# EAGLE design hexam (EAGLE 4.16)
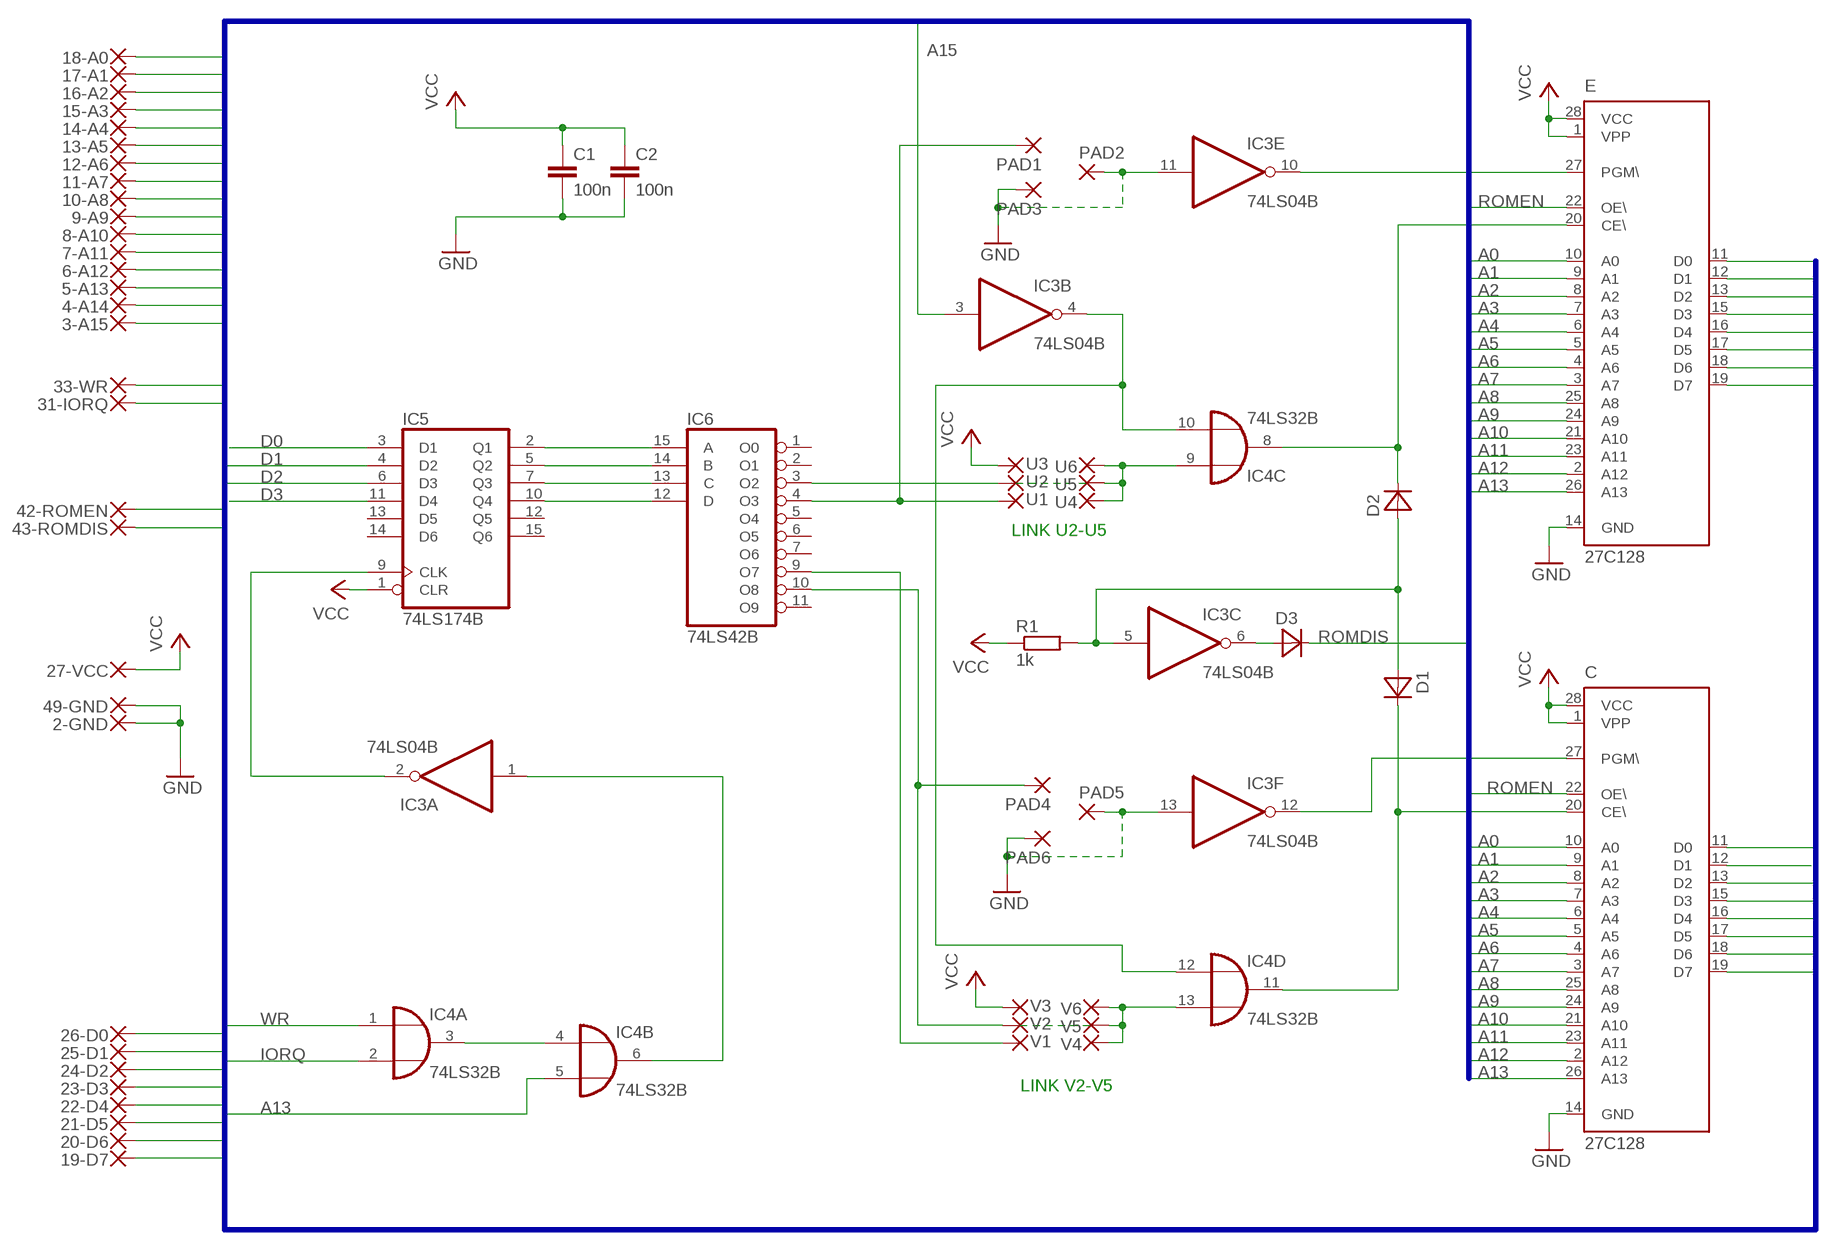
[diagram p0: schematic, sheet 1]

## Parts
2-GND  1,27-REDONDO0.8  [1,27/0,8-REDONDO]
3-A15  1,27-REDONDO0.8  [1,27/0,8-REDONDO]
4-A14  1,27-REDONDO0.8  [1,27/0,8-REDONDO]
5-A13  1,27-REDONDO0.8  [1,27/0,8-REDONDO]
6-A12  1,27-REDONDO0.8  [1,27/0,8-REDONDO]
7-A11  1,27-REDONDO0.8  [1,27/0,8-REDONDO]
8-A10  1,27-REDONDO0.8  [1,27/0,8-REDONDO]
9-A9  1,27-REDONDO0.8  [1,27/0,8-REDONDO]
10-A8  1,27-REDONDO0.8  [1,27/0,8-REDONDO]
11-A7  1,27-REDONDO0.8  [1,27/0,8-REDONDO]
12-A6  1,27-REDONDO0.8  [1,27/0,8-REDONDO]
13-A5  1,27-REDONDO0.8  [1,27/0,8-REDONDO]
14-A4  1,27-REDONDO0.8  [1,27/0,8-REDONDO]
15-A3  1,27-REDONDO0.8  [1,27/0,8-REDONDO]
16-A2  1,27-REDONDO0.8  [1,27/0,8-REDONDO]
17-A1  1,27-REDONDO0.8  [1,27/0,8-REDONDO]
18-A0  1,27-REDONDO0.8  [1,27/0,8-REDONDO]
19-D7  1,27-REDONDO0.8  [1,27/0,8-REDONDO]
20-D6  1,27-REDONDO0.8  [1,27/0,8-REDONDO]
21-D5  1,27-REDONDO0.8  [1,27/0,8-REDONDO]
22-D4  1,27-REDONDO0.8  [1,27/0,8-REDONDO]
23-D3  1,27-REDONDO0.8  [1,27/0,8-REDONDO]
24-D2  1,27-REDONDO0.8  [1,27/0,8-REDONDO]
25-D1  1,27-REDONDO0.8  [1,27/0,8-REDONDO]
26-D0  1,27-REDONDO0.8  [1,27/0,8-REDONDO]
27-VCC  1,27-REDONDO0.8  [1,27/0,8-REDONDO]
31-IORQ  1,27-REDONDO0.8  [1,27/0,8-REDONDO]
33-WR  1,27-REDONDO0.8  [1,27/0,8-REDONDO]
42-ROMEN  1,27-REDONDO0.8  [1,27/0,8-REDONDO]
43-ROMDIS  1,27-REDONDO0.8  [1,27/0,8-REDONDO]
49-GND  1,27-REDONDO0.8  [1,27/0,8-REDONDO]
C  27C128  27128B  [DIL28-6B]
C1  100n  C-EU050-025X075  [C050-025X075]
C2  100n  C-EU050-025X075  [C050-025X075]
D1  DIODE-7,5  [D-7,5]
D2  DIODE-7,5  [D-7,5]
D3  DIODE-7,5  [D-7,5]
E  27C128  27128B  [DIL28-6B]
IC3  74LS04B  [DIL14-B]
IC4  74LS32B  [DIL14-B]
IC5  74LS174B  [DIL16-B]
IC6  74LS42B  [DIL16-B]
PAD1  SMD2  [SMD1,27-2,54]
PAD2  SMD2  [SMD1,27-2,54]
PAD3  SMD2  [SMD1,27-2,54]
PAD4  SMD2  [SMD1,27-2,54]
PAD5  SMD2  [SMD1,27-2,54]
PAD6  SMD2  [SMD1,27-2,54]
R1  1k  R-EU_0207/7  [0207/7]
U1  1,27-REDONDO0.8  [1,27/0,8-REDONDO]
U2  1,27-REDONDO0.8  [1,27/0,8-REDONDO]
U3  1,27-REDONDO0.8  [1,27/0,8-REDONDO]
U4  1,27-REDONDO0.8  [1,27/0,8-REDONDO]
U5  1,27-REDONDO0.8  [1,27/0,8-REDONDO]
U6  1,27-REDONDO0.8  [1,27/0,8-REDONDO]
V1  1,27-REDONDO0.8  [1,27/0,8-REDONDO]
V2  1,27-REDONDO0.8  [1,27/0,8-REDONDO]
V3  1,27-REDONDO0.8  [1,27/0,8-REDONDO]
V4  1,27-REDONDO0.8  [1,27/0,8-REDONDO]
V5  1,27-REDONDO0.8  [1,27/0,8-REDONDO]
V6  1,27-REDONDO0.8  [1,27/0,8-REDONDO]

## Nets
A0: 18-A0.1(P) C.10(A0) E.10(A0)
A1: 17-A1.1(P) C.9(A1) E.9(A1)
A2: 16-A2.1(P) C.8(A2) E.8(A2)
A3: 15-A3.1(P) C.7(A3) E.7(A3)
A4: 14-A4.1(P) C.6(A4) E.6(A4)
A5: 13-A5.1(P) C.5(A5) E.5(A5)
A6: 12-A6.1(P) C.4(A6) E.4(A6)
A7: 11-A7.1(P) C.3(A7) E.3(A7)
A8: 10-A8.1(P) C.25(A8) E.25(A8)
A9: 9-A9.1(P) C.24(A9) E.24(A9)
A10: 8-A10.1(P) C.21(A10) E.21(A10)
A11: 7-A11.1(P) C.23(A11) E.23(A11)
A12: 6-A12.1(P) C.2(A12) E.2(A12)
A13: 5-A13.1(P) C.26(A13) E.26(A13) IC4.5(B:I1)
A14: 4-A14.1(P)
A15: 3-A15.1(P) IC3.3(B:I)
D0: 26-D0.1(P) C.11(D0) E.11(D0) IC5.3(D1)
D1: 25-D1.1(P) C.12(D1) E.12(D1) IC5.4(D2)
D2: 24-D2.1(P) C.13(D2) E.13(D2) IC5.6(D3)
D3: 23-D3.1(P) C.15(D3) E.15(D3) IC5.11(D4)
D4: 22-D4.1(P) C.16(D4) E.16(D4)
D5: 21-D5.1(P) C.17(D5) E.17(D5)
D6: 20-D6.1(P) C.18(D6) E.18(D6)
D7: 19-D7.1(P) C.19(D7) E.19(D7)
GND: 2-GND.1(P) 49-GND.1(P) C1.2 C2.2 C.14(GND) E.14(GND) IC3.11(E:I) IC3.13(F:I) PAD2.1(P) PAD3.1(P) PAD5.1(P) PAD6.1(P)
IORQ: 31-IORQ.1(P) IC4.2(A:I1)
N$5: D1.1(A) D2.1(A) IC3.5(C:I) R1.2
N$12: D3.1(A) IC3.6(C:O)
N$24: C.27(PGM\) IC3.12(F:O)
N$25: D2.2(K) E.20(CE\) IC4.8(C:O)
N$26: E.27(PGM\) IC3.10(E:O)
N$27: IC6.10(O8) PAD4.1(P) V2.1(P)
N$28: IC6.9(O7) V1.1(P)
N$30: IC5.2(Q1) IC6.15(A)
N$31: IC5.5(Q2) IC6.14(B)
N$32: IC5.7(Q3) IC6.13(C)
N$33: IC3.2(A:O) IC5.9(CLK)
N$34: IC6.4(O3) PAD1.1(P) U1.1(P)
N$35: IC6.3(O2) U2.1(P)
N$36: IC4.9(C:I0) U4.1(P) U5.1(P) U6.1(P)
N$37: IC3.1(A:I) IC4.6(B:O)
N$38: IC3.4(B:O) IC4.10(C:I1) IC4.12(D:I0)
N$39: IC4.3(A:O) IC4.4(B:I0)
N$40: IC4.13(D:I1) V4.1(P) V5.1(P) V6.1(P)
N$41: C.20(CE\) D1.2(K) IC4.11(D:O)
N$43: IC5.10(Q4) IC6.12(D)
ROMDIS: 43-ROMDIS.1(P) D3.2(K)
ROMEN: 42-ROMEN.1(P) C.22(OE\) E.22(OE\)
VCC: 27-VCC.1(P) C1.1 C2.1 C.1(VPP) C.28(VCC) E.1(VPP) E.28(VCC) IC5.1(CLR) R1.1 U3.1(P) V3.1(P)
WR: 33-WR.1(P) IC4.1(A:I0)
Unconnected: IC3.8(D:O) IC3.9(D:I) IC5.12(Q5) IC5.13(D5) IC5.14(D6) IC5.15(Q6) IC6.1(O0) IC6.2(O1) IC6.5(O4) IC6.6(O5) IC6.7(O6) IC6.11(O9)

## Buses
A[0..15],WR,IORQ,D[0..7],ROMEN,ROMDIS

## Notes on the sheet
- LINK U2-U5
- LINK V2-V5

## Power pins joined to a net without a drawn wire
GND: IC3.7(P:GND) IC4.7(P:GND) IC5.8(GND) IC6.8(GND)
VCC: IC3.14(P:VCC) IC4.14(P:VCC) IC5.16(VCC) IC6.16(VCC)

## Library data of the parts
2-GND 3-A15 4-A14 5-A13 6-A12 7-A11 8-A10 9-A9 10-A8 11-A7 12-A6 13-A5 14-A4 15-A3 16-A2 17-A1 18-A0 19-D7 20-D6 21-D5 22-D4 23-D3 24-D2 25-D1 26-D0 27-VCC 31-IORQ 33-WR 42-ROMEN 43-ROMDIS 49-GND U1-U6 V1-V6 = wirepad2:1,27-REDONDO
C E = microchip:27*128: CMOS EPROM 128 K (16 K x 8)
C1 C2 = rcl:C-EU: CAPACITOR, European symbol
D1-D3 = discrete2:DIODE-7,5
IC3 = 74xx-eu2:74*04: Hex INVERTER
IC4 = 74xx-eu2:74*32: Quad 2-input OR gate
IC5 = 74xx-eu2:74*174: Hex D type FLIP FLOP, clear
IC6 = 74xx-eu2:74*42: 4-line to 10-line DECODER (1-of-10)
PAD1-PAD6 = wirepad:SMD2: SMD PAD
R1 = rcl:R-EU_: RESISTOR, European symbol

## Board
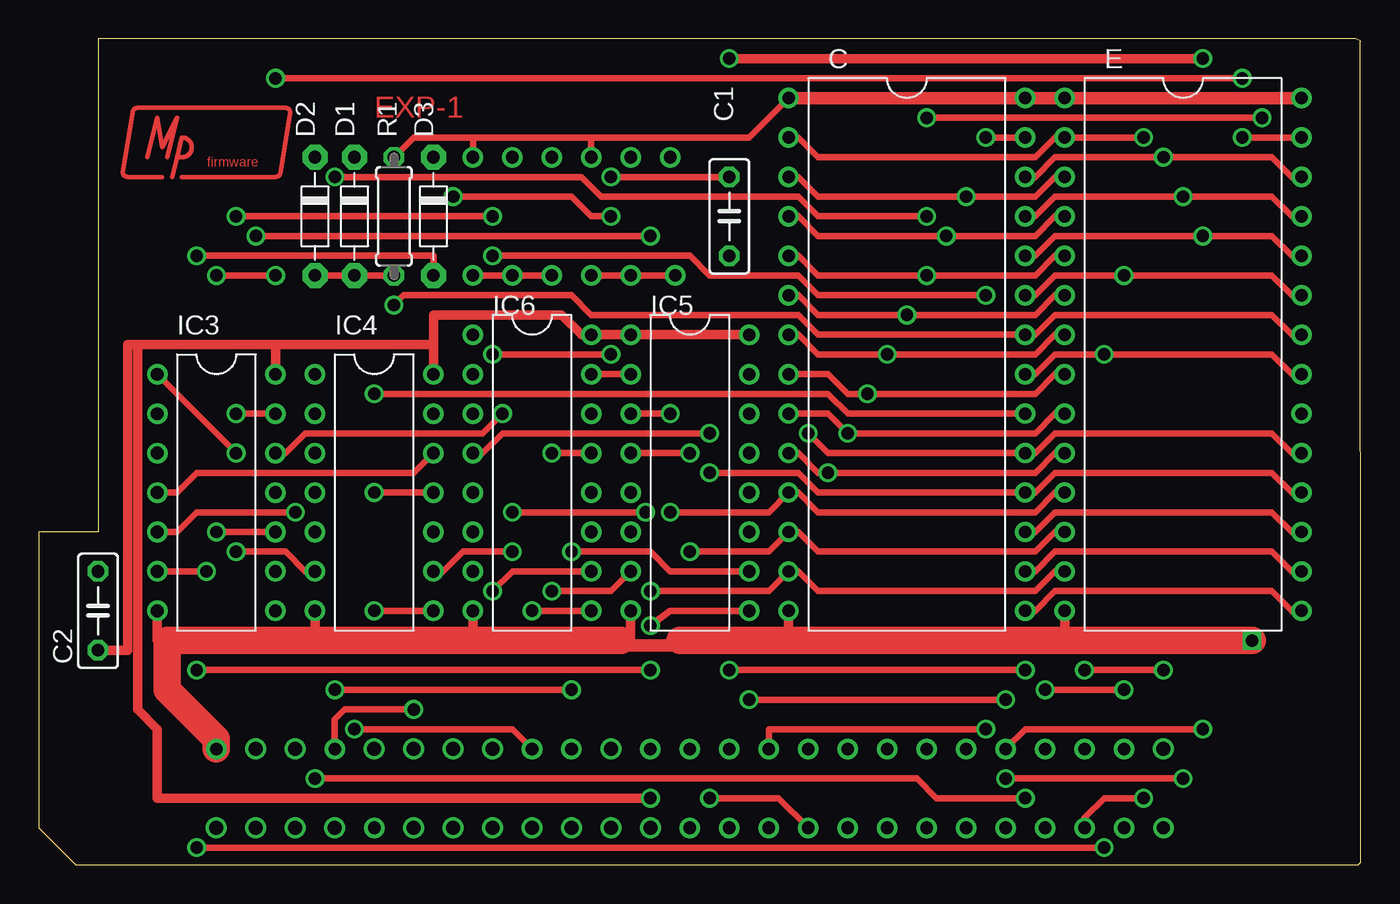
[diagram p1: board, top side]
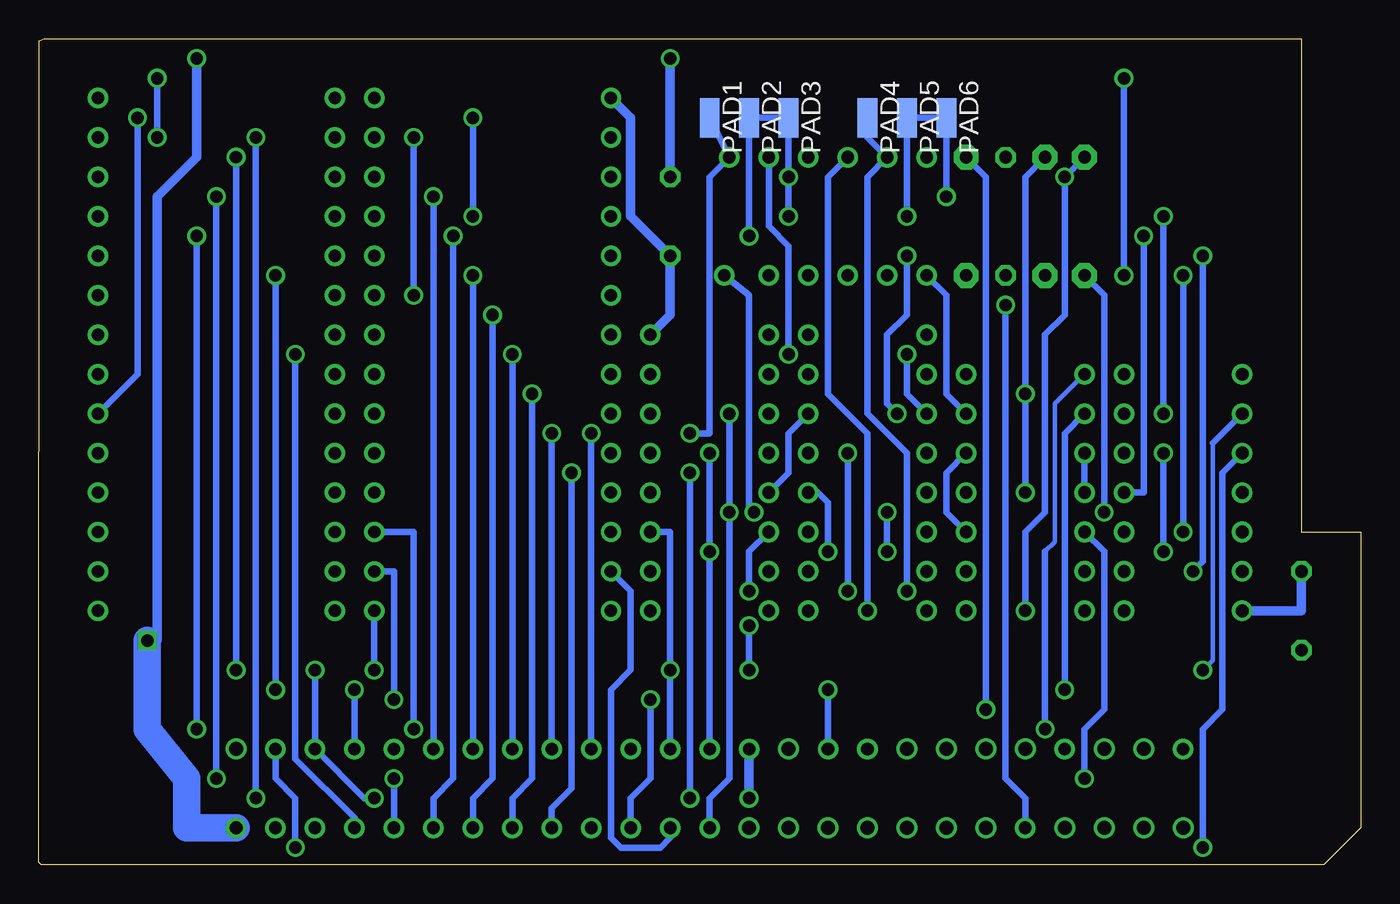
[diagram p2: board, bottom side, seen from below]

Size 85.09 x 53.18 mm. Coordinates in mm from the lower left corner, seen from the top.
Outline: 84.94,0 85.09,0.15 85.08,53.01 85.09,53.01 84.77,53.18 3.81,53.18 3.81,21.43 0,21.43 0,2.38 2.38,0 84.94,0
Copper layers (1*16): Top 0.035mm / dielectric 1.5mm / Bottom 0.035mm
Design rules "default": minimum track width 10mil, minimum drill 24mil, track to track 8mil, track to pad 8mil, pad to pad 8mil, via to via 8mil, smd to smd 8mil, copper to edge 40mil, drill to drill 8mil, minimum pad ring 10mil, minimum via ring 8mil, stop-mask expansion 4mil, vias tented up to drill 0mil, thermal gap 10mil

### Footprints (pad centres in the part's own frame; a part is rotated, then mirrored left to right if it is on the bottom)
1,27/0,8-REDONDO = drill 0.813 pad 1.27 round: 1 0,0
DIL28-6B = drill 0.8 round: 1 -16.51,-7.62; 2 -13.97,-7.62; 3 -11.43,-7.62; 4 -8.89,-7.62; 5 -6.35,-7.62; 6 -3.81,-7.62; 7 -1.27,-7.62; 8 1.27,-7.62; 9 3.81,-7.62; 10 6.35,-7.62; 11 8.89,-7.62; 12 11.43,-7.62; 13 13.97,-7.62; 14 16.51,-7.62; 15 16.51,7.62; 16 13.97,7.62; 17 11.43,7.62; 18 8.89,7.62; 19 6.35,7.62; 20 3.81,7.62; 21 1.27,7.62; 22 -1.27,7.62; 23 -3.81,7.62; 24 -6.35,7.62; 25 -8.89,7.62; 26 -11.43,7.62; 27 -13.97,7.62; 28 -16.51,7.62
C050-025X075 = drill 0.813 octagon: 1 -2.54,0; 2 2.54,0
D-7,5 = drill 0.813 pad 1.6 octagon: 1 -3.81,0; 2 3.81,0
DIL14-B = drill 0.813 round: 1 -7.62,-3.81; 2 -5.08,-3.81; 3 -2.54,-3.81; 4 0,-3.81; 5 2.54,-3.81; 6 5.08,-3.81; 7 7.62,-3.81; 8 7.62,3.81; 9 5.08,3.81; 10 2.54,3.81; 11 0,3.81; 12 -2.54,3.81; 13 -5.08,3.81; 14 -7.62,3.81
DIL16-B = drill 0.813 round: 1 -8.89,-3.81; 2 -6.35,-3.81; 3 -3.81,-3.81; 4 -1.27,-3.81; 5 1.27,-3.81; 6 3.81,-3.81; 7 6.35,-3.81; 8 8.89,-3.81; 9 8.89,3.81; 10 6.35,3.81; 11 3.81,3.81; 12 1.27,3.81; 13 -1.27,3.81; 14 -3.81,3.81; 15 -6.35,3.81; 16 -8.89,3.81
SMD1,27-2,54 = smd 1.27 x 2.54: 1 0,0
0207/7 = drill 0.813 octagon: 1 -3.81,0; 2 3.81,0

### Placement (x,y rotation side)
2-GND  72.39,2.38 180 top
3-A15  69.85,7.46 0 top
4-A14  69.85,2.38 180 top
5-A13  67.31,7.46 0 top
6-A12  67.31,2.38 180 top
7-A11  64.77,7.46 0 top
8-A10  64.77,2.38 180 top
9-A9  62.23,7.46 0 top
10-A8  62.23,2.38 180 top
11-A7  59.69,7.46 0 top
12-A6  59.69,2.38 180 top
13-A5  57.15,7.46 0 top
14-A4  57.15,2.38 180 top
15-A3  54.61,7.46 0 top
16-A2  54.61,2.38 180 top
17-A1  52.07,7.46 0 top
18-A0  52.07,2.38 180 top
19-D7  49.53,7.46 0 top
20-D6  49.53,2.38 180 top
21-D5  46.99,7.46 0 top
22-D4  46.99,2.38 180 top
23-D3  44.45,7.46 0 top
24-D2  44.45,2.38 180 top
25-D1  41.91,7.46 0 top
26-D0  41.91,2.38 180 top
27-VCC  39.37,7.46 0 top
31-IORQ  34.29,7.46 0 top
33-WR  31.75,7.46 0 top
42-ROMEN  21.59,2.38 180 top
43-ROMDIS  19.05,7.46 0 top
49-GND  11.43,7.46 0 top
C  55.88,32.86 270 top
C1  44.45,41.74 90 top
C2  3.81,16.35 90 top
D1  20.32,41.74 90 top
D2  17.78,41.74 90 top
D3  25.4,41.74 90 top
E  73.66,32.86 270 top
IC3  11.43,23.96 270 top
IC4  21.59,23.96 270 top
IC5  41.91,25.23 270 top
IC6  31.75,25.23 270 top
PAD1  41.91,48.09 180 bottom
PAD2  39.37,48.09 180 bottom
PAD3  36.83,48.09 180 bottom
PAD4  31.75,48.09 180 bottom
PAD5  29.21,48.09 180 bottom
PAD6  26.67,48.09 180 bottom
R1  22.86,41.74 270 top
U1  40.64,45.55 0 top
U2  38.1,45.55 0 top
U3  35.56,45.55 0 top
U4  40.96,37.94 0 top
U5  38.1,37.94 0 top
U6  35.56,37.94 0 top
V1  33.02,45.55 0 top
V2  30.48,45.55 0 top
V3  27.94,45.55 0 top
V4  27.94,37.94 0 top
V5  30.48,37.94 0 top
V6  33.02,37.94 0 top

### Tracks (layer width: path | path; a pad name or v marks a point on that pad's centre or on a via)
A0  (via drill 0.8)
  Top 0.406: E.10 65.41,26.51 64.14,25.23 v50.8,25.23 50.16,25.23 48.9,26.51 C.10
  Bottom 0.406: 18-A0.1 52.07,3.65 50.8,4.92 v50.8,25.23
A1  (via drill 0.8)
  Top 0.406: E.9 65.41,29.05 64.14,27.78 v52.07,27.78 50.8,29.05 C.9
  Bottom 0.406: 17-A1.1 v52.07,27.78
A2  (via drill 0.8)
  Top 0.406: E.8 65.41,31.59 64.14,30.32 v53.34,30.32 52.07,30.32 50.8,31.59 C.8
  Bottom 0.406: 16-A2.1 54.61,4.28 53.34,5.55 v53.34,30.32
A3  (via drill 0.8)
  Top 0.406: E.7 65.41,34.12 64.14,32.86 v54.61,32.86 50.16,32.86 48.9,34.12 C.7
  Bottom 0.406: 15-A3.1 v54.61,32.86
A4  (via drill 0.8)
  Top 0.406: E.6 65.41,36.66 64.14,35.4 v55.88,35.4 50.16,35.4 48.9,36.66 C.6
  Bottom 0.406: 14-A4.1 57.15,4.28 55.88,5.55 v55.88,35.4
A5  (via drill 0.8)
  Top 0.406: E.5 65.41,39.2 64.14,37.94 v57.15,37.94 50.16,37.94 48.9,39.2 C.5
  Bottom 0.406: 13-A5.1 v57.15,37.94
A6  (via drill 0.8)
  Top 0.406: E.4 65.41,41.74 64.14,40.48 v58.42,40.48 50.16,40.48 48.9,41.74 C.4
  Bottom 0.406: 12-A6.1 59.69,4.28 58.42,5.55 v58.42,40.48
A7  (via drill 0.8)
  Top 0.406: C.3 48.9,44.29 50.16,43.02 v59.69,43.02 64.14,43.02 65.41,44.29 E.3
  Bottom 0.406: 11-A7.1 v59.69,43.02
A8  (via drill 0.8)
  Top 0.406: E.25 80.64,41.74 79.38,43.02 v73.66,43.02 65.41,43.02 64.14,41.74 C.25 | v62.23,5.55 v73.66,5.55
  Bottom 0.406: v73.66,5.55 v73.66,43.02 | 10-A8.1 v62.23,5.55
A9  (via drill 0.8)
  Top 0.406: E.24 80.64,39.2 79.38,40.48 v74.93,40.48 65.41,40.48 64.14,39.2 C.24 | 9-A9.1 63.5,8.73 v74.93,8.73
  Bottom 0.406: v74.93,8.73 v74.93,40.48
A10  (via drill 0.8)
  Top 0.406: C.21 64.14,31.59 65.41,32.86 v68.58,32.86 79.38,32.86 80.64,31.59 E.21
  Bottom 0.406: 8-A10.1 64.77,3.01 68.58,6.82 v68.58,32.86
A11  (via drill 0.8)
  Top 0.406: E.23 80.64,36.66 79.38,37.94 v69.85,37.94 65.41,37.94 64.14,36.66 C.23 | v64.77,11.27 v69.85,11.27
  Bottom 0.406: 7-A11.1 v64.77,11.27 | v69.85,11.27 v69.85,37.94
A12  (via drill 0.8)
  Top 0.406: C.2 48.9,46.83 50.16,45.55 64.14,45.55 65.41,46.83 E.2 v71.12,46.83 | 6-A12.1 67.31,3.01 68.58,4.28 v71.12,4.28
  Bottom 0.406: v71.12,4.28 v71.12,46.83
A13  (via drill 0.8)
  Top 0.406: E.26 80.64,44.29 79.38,45.55 v72.39,45.55 65.41,45.55 64.14,44.29 C.26 | v67.31,12.54 v72.39,12.54 | v17.78,5.55 56.52,5.55 57.78,4.28 v63.5,4.28
  Bottom 0.406: v67.31,12.54 5-A13.1 64.14,4.28 v63.5,4.28 | v72.39,12.54 v72.39,45.55 | IC4.5 16.51,20.16 16.51,10 17.78,8.73 v17.78,5.55
A15  (via drill 0.8)
  Top 0.406: v10.16,1.1 v68.58,1.1
  Bottom 0.406: IC3.3 8.89,25.23 8.89,10 10.16,8.73 v10.16,1.1 | v68.58,1.1 68.58,4.28 69.85,5.55 3-A15.1
D0  (via drill 0.8)
  Top 0.406: E.11 65.41,23.96 64.14,22.7 50.16,22.7 48.9,23.96 C.11 46.99,22.7 v40.64,22.7 | v40.64,29.05 IC5.3
  Bottom 0.406: 26-D0.1 41.91,4.28 40.64,5.55 v40.64,22.7 v40.64,29.05
D1  (via drill 0.8)
  Top 0.406: E.12 65.41,21.43 64.14,20.16 50.16,20.16 48.9,21.43 C.12 46.99,20.16 v41.91,20.16 | v41.91,26.51 IC5.4
  Bottom 0.406: 25-D1.1 41.91,14.44 v41.91,20.16 v41.91,26.51
D2  (via drill 0.8)
  Top 0.406: E.13 65.41,18.89 64.14,17.62 50.16,17.62 48.9,18.89 C.13 46.99,17.62 v39.37,17.62
  Bottom 0.406: C.13 46.99,17.62 46.99,12.54 48.26,11.27 48.26,1.74 47.62,1.1 45.09,1.1 44.45,1.74 24-D2.1 | IC5.6 39.37,20.16 v39.37,17.62
D3  (via drill 0.8)
  Top 0.406: C.15 64.14,16.35 65.41,17.62 79.38,17.62 80.64,16.35 E.15 | v44.45,12.54 v63.5,12.54
  Bottom 0.406: v63.5,12.54 C.15 | 23-D3.1 v44.45,12.54 44.45,21.43 IC5.11
D4  (via drill 0.8)
  Top 0.406: E.16 80.64,18.89 79.38,20.16 65.41,20.16 64.14,18.89 C.16 | v45.72,10.63 v62.23,10.63
  Bottom 0.406: C.16 62.23,18.89 v62.23,10.63 | v45.72,10.63 45.72,5.55 46.99,4.28 22-D4.1
D5  (via drill 0.8)
  Top 0.406: E.17 80.64,21.43 79.38,22.7 65.41,22.7 64.14,21.43 C.17 | 21-D5.1 46.99,8.73 v60.96,8.73
  Bottom 0.406: v60.96,8.73 60.96,21.43 C.17
D6  (via drill 0.8)
  Top 0.406: E.18 80.64,23.96 79.38,25.23 65.41,25.23 64.14,23.96 C.18 50.16,23.96 48.9,25.23 v43.18,25.23 | v43.18,4.28 47.62,4.28 20-D6.1
  Bottom 0.406: v43.18,4.28 v43.18,25.23
D7  (via drill 0.8)
  Top 0.406: E.19 80.64,26.51 79.38,27.78 65.41,27.78 64.14,26.51 C.19 50.8,26.51 v49.53,27.78
  Bottom 0.406: 19-D7.1 v49.53,27.78
GND  (via drill 0.8)
  Top 0.406: v39.37,40.48 v13.97,40.48 | C1.2 v36.83,44.29 | v36.83,41.74 35.56,41.74 34.29,43.02 v26.67,43.02 | v12.7,29.05 IC3.13 | v29.21,41.74 v12.7,41.74
  Top 0.61: 8.26,14.44 7.62,14.44 IC3.7 | 17.78,14.44 IC4.7 | 27.94,14.44 IC6.8 | 38.1,14.12 IC5.8 | 48.26,14.44 C.14 | 66.04,14.44 E.14 | v74.93,51.91 v44.45,51.91
  Top 0.813: 37.47,14.44 38.1,14.12 40.96,14.12 41.27,14.44
  Top 1.778: 49-GND.1 11.43,8.09 8.26,11.27 8.26,14.44 17.78,14.44 27.94,14.44 37.47,14.44 | 41.27,14.44 48.26,14.44 66.04,14.44 v78.11,14.44
  Bottom 0.406: v39.37,40.48 PAD2.1 PAD3.1 v36.83,44.29 v36.83,41.74 | IC3.11 13.97,23.96 v13.97,40.48 | v26.67,43.02 PAD6.1 PAD5.1 v29.21,41.74 | v12.7,41.74 v12.7,29.05
  Bottom 0.61: C2.2 3.81,16.35 IC3.7 | v78.11,14.44 77.47,14.44 77.47,43.02 74.93,45.55 v74.93,51.91 | v44.45,51.91 C1.2
  Bottom 1.778: 2-GND.1 75.56,2.38 75.56,5.55 78.11,8.73 v78.11,14.44
IORQ  (via drill 0.8)
  Top 0.406: v19.05,11.27 v34.29,11.27
  Bottom 0.406: IC4.2 19.05,27.78 v19.05,11.27 | v34.29,11.27 31-IORQ.1
N$2  (via drill 0.9)
  other vias: 72.39,7.46
N$4  (via drill 0.9)
  other vias: 31.75,2.38
N$5  (via drill 0.8)
  Top 0.406: D2.1 D1.1 R1.2 | v16.51,22.7 10.16,22.7 8.89,21.43 IC3.5
  Bottom 0.406: D2.1 16.51,36.66 v16.51,22.7
N$8  (via drill 0.9)
  other vias: 29.21,7.46
N$9  (via drill 0.9)
  other vias: 26.67,2.38
N$10  (via drill 0.9)
  other vias: 26.67,7.46
N$11  (via drill 0.9)
  other vias: 24.13,7.46
N$12  (via drill 0.8)
  Top 0.406: D3.1 25.4,39.2 v10.16,39.2 | IC3.6 v10.79,18.89
  Bottom 0.406: v10.79,18.89 10.16,19.52 v10.16,39.2
N$13  (via drill 0.9)
  other vias: 19.05,2.38
N$14  (via drill 0.9)
  other vias: 16.51,2.38
N$22  (via drill 0.9)
  other vias: 13.97,2.38
N$23  (via drill 0.9)
  other vias: 13.97,7.46
N$24  (via drill 0.8)
  Top 0.406: v60.96,46.83 C.27 | v60.96,36.66 50.16,36.66 48.9,37.94 43.18,37.94 41.91,39.2 v29.21,39.2 | v29.84,29.05 28.57,27.78 17.14,27.78 15.88,26.51 IC3.12
  Bottom 0.406: v60.96,36.66 v60.96,46.83 | v29.21,39.2 29.21,35.4 30.48,34.12 30.48,29.68 v29.84,29.05
N$25  (via drill 0.8)
  Top 0.406: v57.15,48.09 v78.74,48.09 | v57.15,41.74 50.16,41.74 48.9,43.02 36.2,43.02 34.92,44.29 v19.05,44.29 | v21.59,16.35 IC4.8
  Bottom 0.406: v57.15,41.74 v57.15,48.09 | v78.74,48.09 78.74,31.59 E.20 | v21.59,16.35 21.59,21.43 20.32,22.7 20.32,34.12 19.05,35.4 v19.05,44.29 D2.2
N$26  (via drill 0.8)
  Top 0.406: v77.47,46.83 E.27 | v15.24,50.63 v77.47,50.63 | v11.43,37.94 v15.24,37.94 | v11.43,21.43 IC3.10
  Bottom 0.406: v77.47,50.63 v77.47,46.83 | v15.24,37.94 v15.24,50.63 | v11.43,21.43 v11.43,37.94
N$27  (via drill 0.8)
  Top 0.406: v29.21,17.62 30.48,18.89 IC6.10
  Bottom 0.406: PAD4.1 31.75,46.83 V2.1 31.75,44.29 31.75,29.05 29.21,26.51 v29.21,17.62
N$28  (via drill 0.8)
  Top 0.406: v31.75,16.35 IC6.9
  Bottom 0.406: V1.1 34.29,44.29 34.29,30.32 31.75,27.78 v31.75,16.35
N$29  (via drill 0.9)
  other vias: 11.43,2.38
N$30
  Top 0.406: IC6.15 IC5.2
N$31
  Bottom 0.406: IC5.5 36.83,25.23 36.83,27.78 IC6.14
N$32  (via drill 0.8)
  Top 0.406: IC5.7 36.83,17.62 v33.02,17.62 | v33.02,26.51 IC6.13
  Bottom 0.406: v33.02,17.62 v33.02,26.51
N$33  (via drill 0.8)
  Top 0.406: IC5.9 40.64,16.35 v39.37,15.39 | v10.16,12.54 v39.37,12.54
  Bottom 0.305: v10.16,12.54 9.53,13.17 9.53,27.14
  Bottom 0.406: v39.37,12.54 v39.37,15.39 | 9.53,27.14 IC3.2
N$34  (via drill 0.8)
  Top 0.406: v43.18,27.78 29.84,27.78 28.57,26.51 IC6.4
  Bottom 0.406: v43.18,27.78 41.91,27.78 41.91,44.29 U1.1 PAD1.1
N$35  (via drill 0.8)
  Top 0.406: v29.21,32.86 v36.83,32.86
  Bottom 0.406: U2.1 38.1,41.11 36.83,39.84 v36.83,32.86 | v29.21,32.86 29.21,30.32 IC6.3
N$36  (via drill 0.8)
  Top 0.406: U6.1 U5.1 U4.1 | v30.48,22.7 v39.05,22.7 | v30.48,20.16 27.3,20.16 26.04,18.89 IC4.9
  Bottom 0.406: U4.1 39.37,36.66 39.37,23.01 v39.05,22.7 | v30.48,20.16 v30.48,22.7
N$37  (via drill 0.8)
  Top 0.406: IC4.6 17.14,18.89 15.88,20.16 v12.7,20.16 | v12.7,26.51 IC3.1
  Bottom 0.406: v12.7,20.16 v12.7,26.51
N$38
  Top 0.406: IC4.12 24.13,25.23 10.16,25.23 8.89,23.96 IC3.4
  Bottom 0.406: IC4.12 26.67,25.23 26.67,22.7 IC4.10
N$39
  Bottom 0.406: IC4.4 IC4.3
N$40
  Top 0.406: V4.1 V5.1 V6.1
  Bottom 0.406: IC4.13 26.67,30.32 26.67,36.66 V4.1
N$41  (via drill 0.8)
  Top 0.406: C.20 52.07,29.05 50.8,30.32 v21.59,30.32 | v21.59,23.96 IC4.11
  Bottom 0.406: v21.59,23.96 v21.59,30.32 21.59,44.29 D1.2
N$42  (via drill 0.9)
  other vias: 24.13,2.38
N$43  (via drill 0.8)
  Top 0.406: IC5.10 40.64,18.89 39.37,20.16 v34.29,20.16
  Bottom 0.406: IC6.12 34.92,23.96 34.29,23.33 v34.29,20.16
N$44  (via drill 0.9)
  other vias: 29.21,2.38
N$45  (via drill 0.9)
  other vias: 16.51,7.46
N$46  (via drill 0.9)
  other vias: 21.59,7.46
N$47
  Top 0.305: 7.94,44.29 5.71,44.29 arc-90 5.4,44.6 6.03,48.41 arc-90 6.35,48.73 15.88,48.73 arc-90 16.19,48.41 15.56,44.6 arc-90 15.24,44.29 9.21,44.29
N$48
  Top 0.305: 6.99,45.55 7.62,48.09 7.94,46.19 8.89,48.09 8.26,45.55
N$49
  Top 0.305: 8.57,44.29 8.89,45.55 | 8.89,45.55 9.21,46.83 arc-180 9.21,45.55 8.89,45.55
N$50  (via drill 0.9)
  other vias: 36.83,7.46
N$51  (via drill 0.9)
  other vias: 36.83,2.38
N$52  (via drill 0.9)
  other vias: 34.29,2.38
N$53  (via drill 0.9)
  other vias: 39.37,2.38
ROMDIS  (via drill 0.8)
  Top 0.406: 43-ROMDIS.1 19.05,9.36 19.68,10 v24.13,10
  Bottom 0.406: D3.2 24.13,44.29 v24.13,10
ROMEN  (via drill 0.8)
  Top 0.406: E.22 80.64,34.12 79.38,35.4 65.41,35.4 64.14,34.12 C.22 50.16,34.12 48.9,35.4 35.56,35.4 34.29,36.66 23.5,36.66 v22.86,36.03
  Bottom 0.406: v22.86,36.03 22.86,5.55 21.59,4.28 42-ROMEN.1
VCC  (via drill 0.8)
  Top 0.406: 35.56,46.83 45.72,46.83 C.1 | R1.1 24.13,46.83 27.94,46.83 | 35.56,46.83 27.94,46.83 | 35.56,46.83 U3.1 | 27.94,46.83 V3.1
  Top 0.61: 15.24,33.49 IC3.14 | 15.24,33.49 25.4,33.49 | 25.4,33.49 IC4.14 | 25.4,33.49 25.4,35.4 33.66,35.4 34.92,34.12 IC6.16 IC5.1 IC5.16 | v39.37,4.28 7.62,4.28 7.62,8.73 6.35,10 6.35,33.49 | 6.35,33.49 15.24,33.49 | C2.1 5.71,13.81 5.71,33.49 6.35,33.49
  Top 0.813: E.28 E.1 C.28 C.1
  Bottom 0.61: C.1 46.99,48.09 46.99,41.74 C1.1 44.45,35.4 IC5.16 | v39.37,4.28 27-VCC.1
WR  (via drill 0.8)
  Top 0.406: v20.32,8.73 30.48,8.73 33-WR.1
  Bottom 0.305: IC4.1 19.68,29.68 19.68,20.79 20.32,20.16
  Bottom 0.406: v20.32,8.73 20.32,20.16

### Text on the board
Top: EXP-1 | firmware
